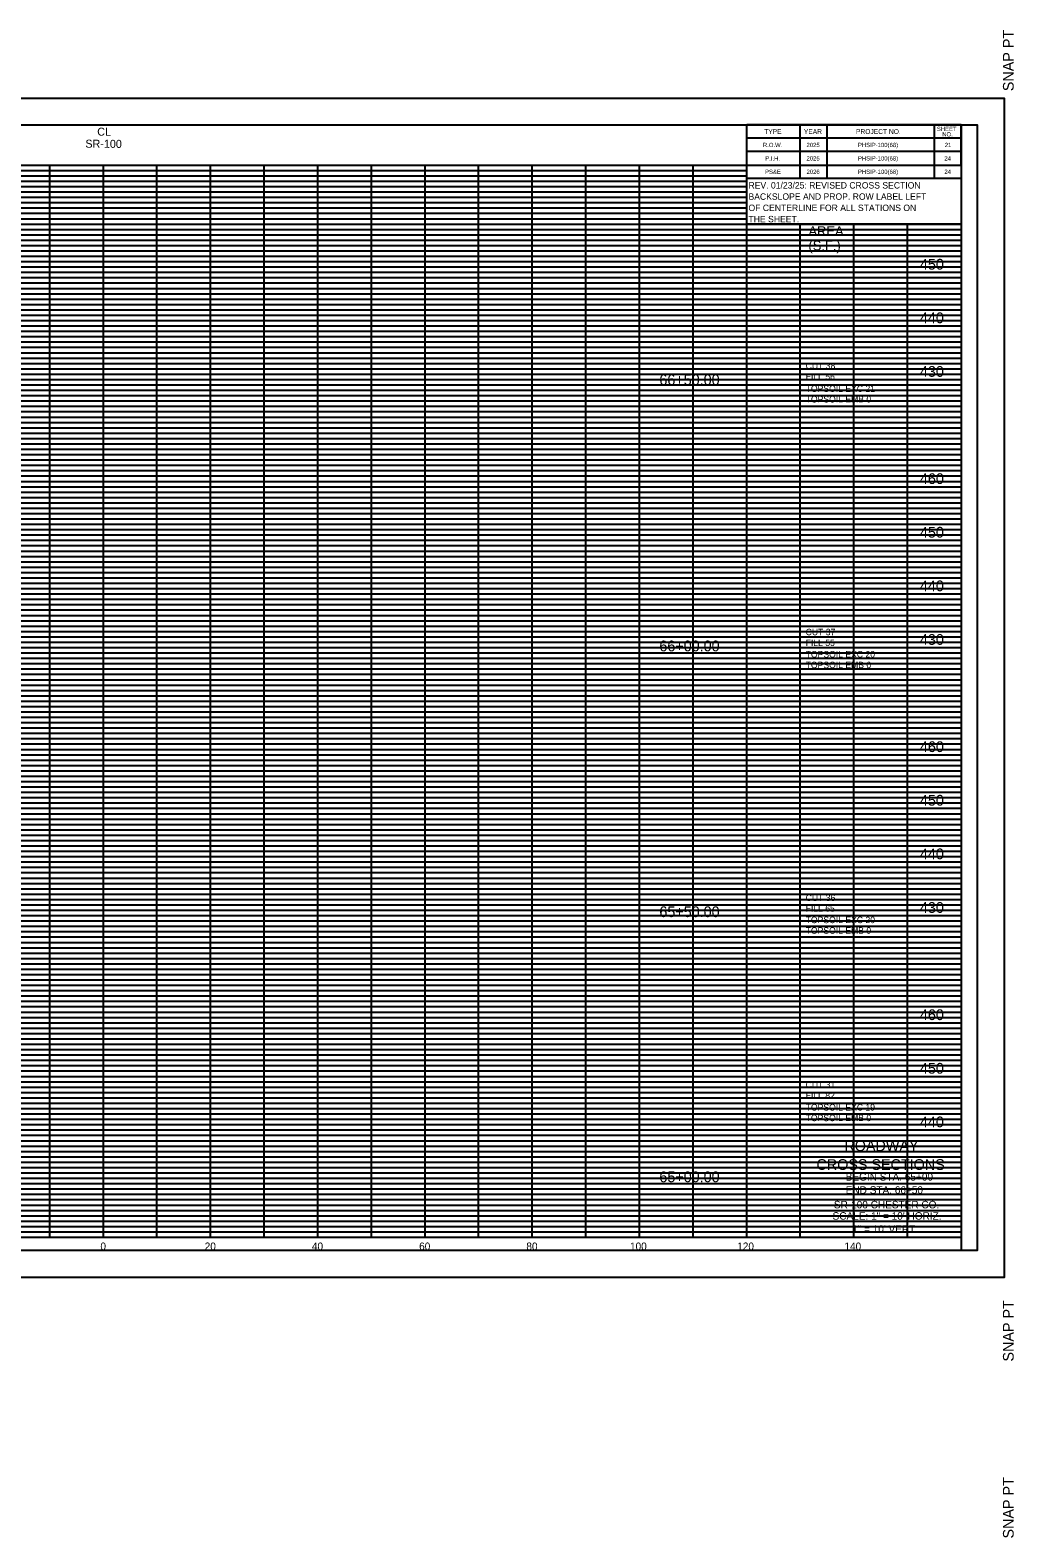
# Model space of a CAD drawing. Extents: x 37 to 1710, y 707 to 2305.
# Drawn here: x 1146.3 to 1329.8, y 2023.9 to 2305.2 of the extents above; entities that cross this region are included whole.
import ezdxf

# ---------------------------------------------------------------- set-up
doc = ezdxf.new("R2010")
doc.units = 0
for name, color, linetype in [('DESIGN - DRAINAGE - Special Ditch Width Text', 7, 'Continuous'), ('DESIGN - SCRATCH - User 1', 7, 'Continuous'), ('DESIGN - SHEET - Corner Text', 7, 'Continuous'), ('DESIGN - SHEET - Light Grid', 7, 'Continuous'), ('DESIGN - SHEET - Linework', 7, 'Continuous'), ('DESIGN - SHEET - Plot Shape', 7, 'Continuous'), ('DESIGN - TITLE SHEET - PROJECT LENGTH - ROW', 7, 'Continuous'), ('DESIGN - TYPICAL - Text', 7, 'Continuous')]:
    doc.layers.add(name, color=color, linetype=linetype)

msp = doc.modelspace()

# ---------------------------------------------------------------- linework, layer by layer
at = {"layer": 'DESIGN - SCRATCH - User 1'}
for p, q in [((1285, 2283.75), (1285, 2283.75)), ((1285, 2281.25), (1285, 2281.25)), ((1292.5, 2283.75), (1292.5, 2283.75)), ((1292.5, 2281.25), (1292.5, 2281.25)), ((1305, 2283.75), (1305, 2283.75)), ((1305, 2281.25), (1305, 2281.25)), ((1317.5, 2283.75), (1317.5, 2283.75)), ((1317.5, 2281.25), (1317.5, 2281.25))]:
    msp.add_line(p, q, dxfattribs=at)
at = {"layer": 'DESIGN - SHEET - Light Grid'}
for p, q in [((1000, 2279), (1280, 2279)), ((1000, 2278), (1280, 2278)), ((1000, 2277), (1280, 2277)), ((1000, 2276), (1280, 2276)), ((1000, 2275), (1280, 2275)), ((1000, 2274), (1280, 2274)), ((1000, 2273), (1280, 2273)), ((1000, 2272), (1280, 2272)), ((1000, 2271), (1280, 2271)), ((1000, 2269), (1320, 2269)), ((1000, 2268), (1320, 2268)), ((1000, 2267), (1320, 2267)), ((1000, 2266), (1320, 2266)), ((1000, 2265), (1320, 2265)), ((1000, 2264), (1320, 2264)), ((1000, 2263), (1320, 2263)), ((1000, 2262), (1320, 2262)), ((1000, 2261), (1320, 2261)), ((1000, 2259), (1320, 2259)), ((1000, 2258), (1320, 2258)), ((1000, 2257), (1320, 2257)), ((1000, 2256), (1320, 2256)), ((1000, 2255), (1320, 2255)), ((1000, 2254), (1320, 2254)), ((1000, 2253), (1320, 2253)), ((1000, 2252), (1320, 2252)), ((1000, 2251), (1320, 2251)), ((1000, 2249), (1320, 2249)), ((1000, 2248), (1320, 2248)), ((1000, 2247), (1320, 2247)), ((1000, 2246), (1320, 2246)), ((1000, 2245), (1320, 2245)), ((1000, 2244), (1320, 2244)), ((1000, 2243), (1320, 2243)), ((1000, 2242), (1320, 2242)), ((1000, 2241), (1320, 2241)), ((1000, 2239), (1320, 2239)), ((1000, 2238), (1320, 2238)), ((1000, 2237), (1320, 2237)), ((1000, 2236), (1320, 2236)), ((1000, 2235), (1320, 2235)), ((1000, 2234), (1320, 2234)), ((1000, 2233), (1320, 2233)), ((1000, 2232), (1320, 2232)), ((1000, 2231), (1320, 2231)), ((1000, 2229), (1320, 2229)), ((1000, 2228), (1320, 2228)), ((1000, 2227), (1320, 2227)), ((1000, 2226), (1320, 2226)), ((1000, 2225), (1320, 2225)), ((1000, 2224), (1320, 2224)), ((1000, 2223), (1320, 2223)), ((1000, 2222), (1320, 2222)), ((1000, 2221), (1320, 2221)), ((1000, 2219), (1320, 2219)), ((1000, 2218), (1320, 2218)), ((1000, 2217), (1320, 2217)), ((1000, 2216), (1320, 2216)), ((1000, 2215), (1320, 2215)), ((1000, 2214), (1320, 2214)), ((1000, 2213), (1320, 2213)), ((1000, 2212), (1320, 2212)), ((1000, 2211), (1320, 2211)), ((1000, 2209), (1320, 2209)), ((1000, 2208), (1320, 2208)), ((1000, 2207), (1320, 2207)), ((1000, 2206), (1320, 2206)), ((1000, 2205), (1320, 2205)), ((1000, 2204), (1320, 2204)), ((1000, 2203), (1320, 2203)), ((1000, 2202), (1320, 2202)), ((1000, 2201), (1320, 2201)), ((1000, 2199), (1320, 2199)), ((1000, 2198), (1320, 2198)), ((1000, 2197), (1320, 2197)), ((1000, 2196), (1320, 2196)), ((1000, 2195), (1320, 2195)), ((1000, 2194), (1320, 2194)), ((1000, 2193), (1320, 2193)), ((1000, 2192), (1320, 2192)), ((1000, 2191), (1320, 2191)), ((1000, 2189), (1320, 2189)), ((1000, 2188), (1320, 2188)), ((1000, 2187), (1320, 2187)), ((1000, 2186), (1320, 2186)), ((1000, 2185), (1320, 2185)), ((1000, 2184), (1320, 2184)), ((1000, 2183), (1320, 2183)), ((1000, 2182), (1320, 2182)), ((1000, 2181), (1320, 2181)), ((1000, 2179), (1320, 2179)), ((1000, 2178), (1320, 2178)), ((1000, 2177), (1320, 2177)), ((1000, 2176), (1320, 2176)), ((1000, 2175), (1320, 2175)), ((1000, 2174), (1320, 2174)), ((1000, 2173), (1320, 2173)), ((1000, 2172), (1320, 2172)), ((1000, 2171), (1320, 2171)), ((1000, 2169), (1320, 2169)), ((1000, 2168), (1320, 2168)), ((1000, 2167), (1320, 2167)), ((1000, 2166), (1320, 2166)), ((1000, 2165), (1320, 2165)), ((1000, 2164), (1320, 2164)), ((1000, 2163), (1320, 2163)), ((1000, 2162), (1320, 2162)), ((1000, 2161), (1320, 2161)), ((1000, 2159), (1320, 2159)), ((1000, 2158), (1320, 2158)), ((1000, 2157), (1320, 2157)), ((1000, 2156), (1320, 2156)), ((1000, 2155), (1320, 2155)), ((1000, 2154), (1320, 2154)), ((1000, 2153), (1320, 2153)), ((1000, 2152), (1320, 2152)), ((1000, 2151), (1320, 2151)), ((1000, 2149), (1320, 2149)), ((1000, 2148), (1320, 2148)), ((1000, 2147), (1320, 2147)), ((1000, 2146), (1320, 2146)), ((1000, 2145), (1320, 2145)), ((1000, 2144), (1320, 2144)), ((1000, 2143), (1320, 2143)), ((1000, 2142), (1320, 2142)), ((1000, 2141), (1320, 2141)), ((1000, 2139), (1320, 2139)), ((1000, 2138), (1320, 2138)), ((1000, 2137), (1320, 2137)), ((1000, 2136), (1320, 2136)), ((1000, 2135), (1320, 2135)), ((1000, 2134), (1320, 2134)), ((1000, 2133), (1320, 2133)), ((1000, 2132), (1320, 2132)), ((1000, 2131), (1320, 2131)), ((1000, 2129), (1320, 2129)), ((1000, 2128), (1320, 2128)), ((1000, 2127), (1320, 2127)), ((1000, 2126), (1320, 2126)), ((1000, 2125), (1320, 2125)), ((1000, 2124), (1320, 2124)), ((1000, 2123), (1320, 2123)), ((1000, 2122), (1320, 2122)), ((1000, 2121), (1320, 2121)), ((1000, 2119), (1320, 2119)), ((1000, 2118), (1320, 2118)), ((1000, 2117), (1320, 2117)), ((1000, 2116), (1320, 2116)), ((1000, 2115), (1320, 2115)), ((1000, 2114), (1320, 2114)), ((1000, 2113), (1320, 2113)), ((1000, 2112), (1320, 2112)), ((1000, 2111), (1320, 2111)), ((1000, 2109), (1320, 2109)), ((1000, 2108), (1320, 2108)), ((1000, 2107), (1320, 2107)), ((1000, 2106), (1320, 2106)), ((1000, 2105), (1320, 2105)), ((1000, 2104), (1320, 2104)), ((1000, 2103), (1320, 2103)), ((1000, 2102), (1320, 2102)), ((1000, 2101), (1320, 2101)), ((1000, 2099), (1320, 2099)), ((1000, 2098), (1320, 2098)), ((1000, 2097), (1320, 2097)), ((1000, 2096), (1320, 2096)), ((1000, 2095), (1320, 2095)), ((1000, 2094), (1320, 2094)), ((1000, 2093), (1320, 2093)), ((1000, 2092), (1320, 2092)), ((1000, 2091), (1320, 2091)), ((1000, 2089), (1320, 2089)), ((1000, 2088), (1320, 2088)), ((1000, 2087), (1320, 2087)), ((1000, 2086), (1320, 2086)), ((1000, 2085), (1320, 2085)), ((1000, 2084), (1320, 2084)), ((1000, 2083), (1320, 2083)), ((1000, 2082), (1320, 2082)), ((1000, 2081), (1320, 2081))]:
    msp.add_line(p, q, dxfattribs=at)
at = {"layer": 'DESIGN - SHEET - Linework'}
for p, q in [((1320, 2287.5), (1280, 2287.5)), ((1280, 2280), (1280, 2287.5)), ((1290, 2277.5), (1290, 2287.5)), ((1295, 2277.5), (1295, 2287.5)), ((1315, 2277.5), (1315, 2287.5)), ((1320, 2280), (1320, 2287.5)), ((1320, 2285), (1280, 2285)), ((1320, 2282.5), (1280, 2282.5)), ((1000, 2280), (1320, 2280)), ((1150, 2080), (1150, 2280)), ((1160, 2080), (1160, 2280)), ((1170, 2080), (1170, 2280)), ((1180, 2080), (1180, 2280)), ((1190, 2080), (1190, 2280)), ((1200, 2080), (1200, 2280)), ((1210, 2080), (1210, 2280)), ((1220, 2080), (1220, 2280)), ((1230, 2080), (1230, 2280)), ((1240, 2080), (1240, 2280)), ((1250, 2080), (1250, 2280)), ((1260, 2080), (1260, 2280)), ((1270, 2080), (1270, 2280)), ((1280, 2080), (1280, 2280)), ((1320, 2277.5), (1280, 2277.5)), ((1000, 2270), (1280, 2270)), ((1320, 2269), (1280, 2269)), ((1290, 2080), (1290, 2269)), ((1300, 2080), (1300, 2269)), ((1310, 2080), (1310, 2269)), ((1000, 2260), (1320, 2260)), ((1000, 2250), (1320, 2250)), ((1000, 2240), (1320, 2240)), ((1000, 2230), (1320, 2230)), ((1000, 2220), (1320, 2220)), ((1000, 2210), (1320, 2210)), ((1000, 2200), (1320, 2200)), ((1000, 2190), (1320, 2190)), ((1000, 2180), (1320, 2180)), ((1000, 2170), (1320, 2170)), ((1000, 2160), (1320, 2160)), ((1000, 2150), (1320, 2150)), ((1000, 2140), (1320, 2140)), ((1000, 2130), (1320, 2130)), ((1000, 2120), (1320, 2120)), ((1000, 2110), (1320, 2110)), ((1000, 2100), (1320, 2100)), ((1000, 2090), (1320, 2090)), ((1000, 2080), (1320, 2080))]:
    msp.add_line(p, q, dxfattribs=at)
for points in [[(988, 2292.5), (1328, 2292.5), (1328, 2072.5), (988, 2072.5)], [(1000, 2287.5), (1320, 2287.5), (1320, 2077.5), (1000, 2077.5)]]:
    msp.add_lwpolyline(points, close=True, dxfattribs=at)
at = {"layer": 'DESIGN - SHEET - Plot Shape'}
msp.add_lwpolyline([(993, 2287.5), (1323, 2287.5), (1323, 2077.5), (993, 2077.5)], close=True, dxfattribs=at)

# ---------------------------------------------------------------- texts
at = {"layer": 'DESIGN - DRAINAGE - Special Ditch Width Text'}
for s, p in [('CL', (1158.85, 2285.48)), ('SR-100', (1156.64, 2283.24))]:
    msp.add_text(s, height=1.5, rotation=359.6675, dxfattribs=at).set_placement(p)
at = {"layer": 'DESIGN - SHEET - Corner Text'}
for s, p in [('  SNAP PT', (1329.8, 2292.3)), ('SNAP PT  ', (1329.8, 2056.8)), ('  SNAP PT', (1329.8, 2022.3))]:
    msp.add_text(s, height=2, rotation=90, dxfattribs=at).set_placement(p)
for s, height, p in [('R.O.W.', 0.8, (1283.02, 2283.35)), ('2025', 0.8, (1291.16, 2283.35)), ('PHSIP-100(68)', 0.8, (1300.75, 2283.35)), ('21', 0.8, (1316.94, 2283.35)), ('P.I.H.', 0.8, (1283.45, 2280.85)), ('2025', 0.8, (1291.16, 2280.85)), ('PHSIP-100(68)', 0.8, (1300.75, 2280.85)), ('24', 0.8, (1316.87, 2280.85)), ('PS&E', 0.8, (1283.42, 2278.35)), ('2026', 0.8, (1291.16, 2278.35)), ('PHSIP-100(68)', 0.8, (1300.75, 2278.35)), ('24', 0.8, (1316.87, 2278.35)), ('ROADWAY ', 2, (1298.23, 2096.05)), ('CROSS SECTIONS', 2, (1293.01, 2092.55)), ('BEGIN STA. 65+00', 1.4, (1298.47, 2090.55)), ('END STA. 66+50', 1.4, (1298.47, 2088.1)), ('SCALE: 1" = 10\' HORIZ.', 1.4, (1296.02, 2083.26)), ('SR-100 CHESTER CO.', 1.4, (1296.25, 2085.37)), ('       1" = 10\' VERT.   ', 1.4, (1296.02, 2080.81))]:
    msp.add_text(s, height=height, dxfattribs=at).set_placement(p)
at = {"layer": 'DESIGN - SHEET - Light Grid'}
for s, height, p in [('TYPE', 0.9, (1283.26, 2285.8)), ('YEAR', 0.9, (1290.66, 2285.8)), ('PROJECT NO.', 0.9, (1300.38, 2285.8)), ('SHEET', 0.8, (1315.47, 2286.35)), ('NO.', 0.8, (1316.47, 2285.35))]:
    msp.add_text(s, height=height, dxfattribs=at).set_placement(p)
at = {"layer": 'DESIGN - TITLE SHEET - PROJECT LENGTH - ROW'}
for s, p in [('REV. 01/23/25: REVISED CROSS SECTION ', (1280.33, 2275.62)), ('OF CENTERLINE FOR ALL STATIONS ON ', (1280.33, 2271.42)), ('BACKSLOPE AND PROP. ROW LABEL LEFT ', (1280.33, 2273.52)), ('THE SHEET.', (1280.33, 2269.32))]:
    msp.add_text(s, height=1.2, rotation=0, dxfattribs=at).set_placement(p)
at = {"layer": 'DESIGN - TYPICAL - Text'}
for s, height, p in [('AREA ', 1.8, (1291.52, 2266.79)), ('(S.F.)', 1.8, (1291.52, 2264.09)), ('     450     ', 2, (1308.6, 2260.5)), ('     440     ', 2, (1308.6, 2250.5)), ('CUT 38', 1.2, (1291, 2241.95)), ('     430     ', 2, (1308.6, 2240.5)), ('     66+50.00     ', 2, (1260, 2238.95)), ('TOPSOIL EXC 21', 1.2, (1291, 2237.69)), ('FILL 56', 1.2, (1291, 2239.95)), ('TOPSOIL EMB 0', 1.2, (1291, 2235.71)), ('     460     ', 2, (1308.6, 2220.5)), ('     450     ', 2, (1308.6, 2210.5)), ('     440     ', 2, (1308.6, 2200.5)), ('     66+00.00     ', 2, (1260, 2189.29)), ('CUT 37', 1.2, (1291, 2192.29)), ('FILL 55', 1.2, (1291, 2190.29)), ('     430     ', 2, (1308.6, 2190.5)), ('TOPSOIL EXC 20', 1.2, (1291, 2188.14)), ('TOPSOIL EMB 0', 1.2, (1291, 2186.15)), ('     460     ', 2, (1308.6, 2170.5)), ('     450     ', 2, (1308.6, 2160.5)), ('     440     ', 2, (1308.6, 2150.5)), ('CUT 36', 1.2, (1291, 2142.71)), ('     65+50.00     ', 2, (1260, 2139.71)), ('FILL 65', 1.2, (1291, 2140.71)), ('     430     ', 2, (1308.6, 2140.5)), ('TOPSOIL EXC 20', 1.2, (1291, 2138.58)), ('TOPSOIL EMB 0', 1.2, (1291, 2136.6)), ('     460     ', 2, (1308.6, 2120.5)), ('     450     ', 2, (1308.6, 2110.5)), ('CUT 31', 1.2, (1291, 2107.84)), ('FILL 82', 1.2, (1291, 2105.84)), ('TOPSOIL EXC 19', 1.2, (1291, 2103.62)), ('TOPSOIL EMB 0', 1.2, (1291, 2101.64)), ('     440     ', 2, (1308.6, 2100.5)), ('     65+00.00     ', 2, (1260, 2090.25)), ('     0     ', 1.4, (1156.85, 2077.6)), ('     0     ', 1.4, (1156.85, 2077.6)), ('     20     ', 1.4, (1176.3, 2077.6)), ('     40     ', 1.4, (1196.3, 2077.6)), ('     60     ', 1.4, (1216.3, 2077.6)), ('     80     ', 1.4, (1236.3, 2077.6)), ('     100     ', 1.4, (1255.63, 2077.6)), ('     120     ', 1.4, (1275.63, 2077.6)), ('     140     ', 1.4, (1295.63, 2077.6))]:
    msp.add_text(s, height=height, dxfattribs=at).set_placement(p)

doc.saveas('drawing.dxf')
